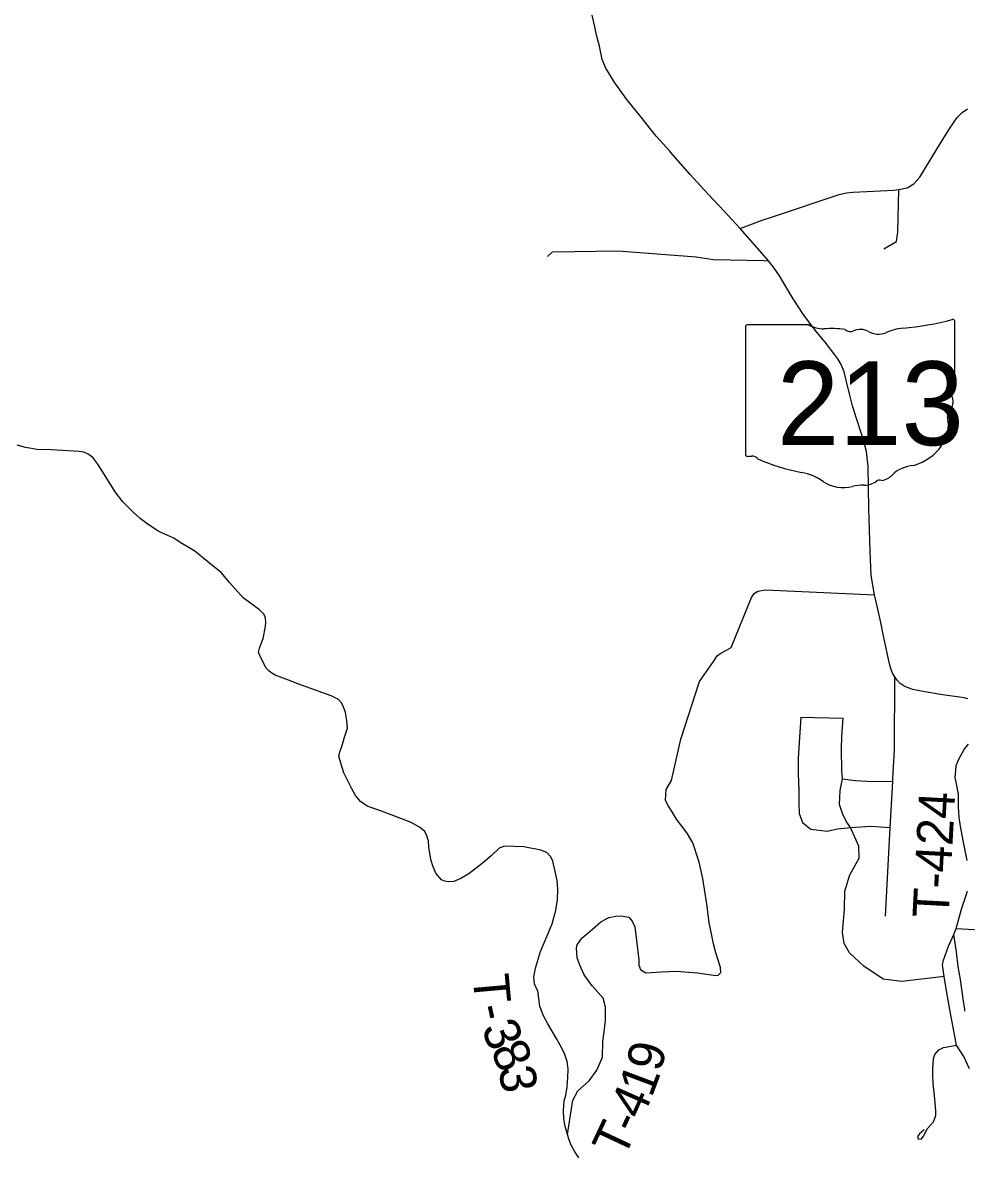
# Model space of a CAD drawing. Extents: x 2402298 to 2498138, y 789485 to 950881.
# Drawn here: x 2476688 to 2484526, y 874577 to 883995 of the extents above; entities that cross this region are included whole.
import ezdxf

# ---------------------------------------------------------------- set-up
doc = ezdxf.new("R2010")
doc.units = 0
for name, color, linetype in [('GM_X_State_Route', 7, 'Continuous'), ('GM_X_State_Shield', 7, 'Continuous'), ('GM_X_Township_Road', 7, 'Continuous'), ('GM_X_Township_Road_Text', 7, 'Continuous')]:
    doc.layers.add(name, color=color, linetype=linetype)

msp = doc.modelspace()

# ---------------------------------------------------------------- linework, layer by layer
at = {"layer": 'GM_X_State_Route'}
for points in [[(2482062.4, 882927.1), (2481950.2, 883051.3), (2481826.2, 883210.2), (2481705.4, 883356.5), (2481606.8, 883496.4), (2481530.5, 883617.2), (2481501.9, 883689.1), (2481479.4, 883800.2), (2481455, 883892.2), (2481439.4, 883959.9), (2481418.6, 884057.1)], [(2482646.9, 882284.5), (2482516.1, 882429.7), (2482346, 882609.4), (2482233.2, 882733.3), (2482069.4, 882919.3), (2482062.4, 882927.1)], [(2483763, 879242.9), (2483735.5, 879402), (2483727.3, 879605.7), (2483716.4, 879957.8), (2483710, 880308.3), (2483697.6, 880431.4), (2483675.6, 880514.4), (2483657.3, 880570), (2483613.4, 880706.9), (2483582.1, 880811.3), (2483558.2, 880900.3), (2483529.3, 881026.4), (2483511.1, 881094.2), (2483486.6, 881154.1), (2483459.6, 881201.3), (2483434.5, 881236.4), (2483352.8, 881340.2), (2483281.8, 881425.7), (2483226.1, 881498.2), (2483171.7, 881573), (2483086.5, 881700.7), (2482973.7, 881890.6), (2482923.9, 881963.5), (2482881.8, 882017), (2482831.2, 882078.5), (2482646.9, 882284.5)], [(2484540.1, 878377.2), (2484509.2, 878385.2), (2484312.9, 878413), (2484181.9, 878435.5), (2484081.1, 878456), (2484043.1, 878467.7), (2484011.1, 878483), (2483977.4, 878506), (2483951.1, 878532.5), (2483931.4, 878560.1), (2483913.9, 878591.3), (2483900.9, 878622.3), (2483890.6, 878655.8), (2483873.3, 878731.7), (2483851.9, 878838), (2483833.9, 878924.8), (2483815.8, 879011.1), (2483784.5, 879148.4), (2483763, 879242.9)]]:
    msp.add_lwpolyline(points, dxfattribs=at)
at = {"layer": 'GM_X_State_Shield'}
for p, q in [((2484431.7, 880958.8), (2484431.7, 881511.5)), ((2482691.5, 881467.2), (2482691.5, 880410.5)), ((2483218.3, 881485.3), (2482708.6, 881485.3)), ((2484431.5, 880958.9), (2484431.7, 880958.8))]:
    msp.add_line(p, q, dxfattribs=at)
for centre, major_axis, start_param, end_param in [((2483811.8, 882925.9), (1845.5, 0), 4.814394, 5.042369), ((2484412.4, 881513.8), (19.4, 0), 6.141152, 7.989035), ((2482711.4, 881469.4), (20.2, 0), 1.712693, 3.28349), ((2483339.6, 881608), (195.5, 0), 4.042523, 4.731795), ((2483404.5, 880892.1), (702, 0), 1.404758, 1.657858), ((2483563.8, 881474.9), (56.4, 0), 3.836095, 5.185415), ((2483646.6, 881352.8), (117.3, 0), 0.950623, 2.079405), ((2483798, 881520.3), (141.1, 0), 4.081561, 5.145723), ((2484047.2, 881162.6), (371.3, 0), 1.699011, 2.107814), ((2484427.2, 880918.2), (30, 0), 1.883978, 3.671073), ((2484411, 880956.6), (20.7, 0), 5.05454, 6.418171), ((2484236.5, 880848.3), (180, 0), 5.934695, 6.695948), ((2484501.1, 880727.5), (130.9, 0), 2.387724, 3.262537), ((2483915.2, 880657.2), (461.6, 0), 5.101752, 6.440018), ((2482711.6, 880408.2), (20.3, 0), 3.00124, 4.508301), ((2482714.7, 880516.3), (155.2, 0), 4.665946, 4.897461), ((2482746.5, 880349.6), (56, 0), 0.519207, 1.627899), ((2483453.1, 881298.9), (1332.7, 0), 4.195997, 4.488961), ((2484109.8, 880113.9), (252.8, 0), 1.647645, 2.488434), ((2483055.7, 879935.8), (417, 0), 0.823519, 1.323587), ((2483506.7, 880344.3), (264.6, 0), 4.026481, 4.996735), ((2483678.9, 880265.2), (141, 0), 4.691044, 5.507374), ((2483806.5, 880162.9), (39.7, 0), 1.147584, 2.315152), ((2483789.5, 880308.1), (149.1, 0), 4.937069, 5.64225), ((2483659.6, 879979), (217.4, 0), 1.495662, 1.94098)]:
    msp.add_ellipse(centre, major_axis=major_axis, ratio=0.8, start_param=start_param, end_param=end_param, dxfattribs=at)
at = {"layer": 'GM_X_Township_Road'}
for p, q in [((2483150.3, 878223.8), (2483503.5, 878215.5)), ((2484440.6, 876468.1), (2484743.1, 876451.3))]:
    msp.add_line(p, q, dxfattribs=at)
for points in [[(2482646.9, 882284.5), (2482831, 882353.7), (2482925, 882386.1), (2483470.4, 882567.8), (2483529.6, 882580.3), (2483584.3, 882586.5), (2483758.6, 882595.5), (2483919.6, 882603.1), (2483965.1, 882607.8), (2484035.8, 882622.1), (2484091.2, 882655.4), (2484139.1, 882711.1), (2484226.6, 882854.1), (2484280.6, 882943.1), (2484381.2, 883103.7), (2484418.8, 883162.8), (2484450.1, 883206.6), (2484492.6, 883248.3), (2484537, 883279.9)], [(2483841.8, 882115), (2483945.2, 882177), (2483957.9, 882254.9), (2483965.1, 882607.8)], [(2481048.6, 882051.5), (2481090.2, 882091.9), (2481635.5, 882098.3), (2482282.4, 882050.6), (2482427.1, 882028.3), (2482844.4, 882017.9), (2482881.8, 882017)], [(2481112.8, 876606.4), (2481129.7, 876706.6), (2481132.4, 876796.9), (2481126.7, 876868.6), (2481112.2, 876942.1), (2481090.5, 877028.2), (2481074.9, 877065.8), (2481042.7, 877099.8), (2480992.4, 877119), (2480851.6, 877146.6), (2480691.2, 877152.1), (2480645.4, 877135.6), (2480578.4, 877073.2), (2480505.7, 877009.6), (2480393, 876924.7), (2480327.4, 876885.3), (2480269.7, 876860.3), (2480221.3, 876857), (2480194.2, 876861.8), (2480167.3, 876873.5), (2480118.4, 876928.1), (2480097.9, 876982.4), (2480077.4, 877043.1), (2480062.8, 877144.8), (2480060, 877198.2), (2480044.4, 877238.1), (2480027.7, 877275.6), (2479985.2, 877312.4), (2479916.2, 877348.8), (2479828.4, 877384.1), (2479667.3, 877444.8), (2479549.4, 877485), (2479492.9, 877524.1), (2479453.8, 877574.5), (2479420.8, 877629.2), (2479355.9, 877763.8), (2479314.9, 877899.3), (2479322.9, 877937.6), (2479339.2, 877981.6), (2479362, 878058.6), (2479385.1, 878132.5), (2479380.7, 878196.7), (2479369.9, 878263.8), (2479350.6, 878316.5), (2479333.9, 878347.2), (2479312.5, 878373.2), (2479251, 878401.9), (2478972.9, 878502.2), (2478895.1, 878531.2), (2478784.2, 878574.9), (2478757.7, 878590.8), (2478734.6, 878607.9), (2478711.1, 878633.1), (2478677, 878694.8), (2478648, 878761.7), (2478657, 878806.8), (2478684.7, 878879.5), (2478705.3, 878977.9), (2478706.6, 879015.3), (2478705.9, 879048.1), (2478693, 879079), (2478654.4, 879117.6), (2478520.6, 879216.7), (2478406.7, 879342.8), (2478338.5, 879423.9), (2478226.5, 879516.5), (2478118.4, 879605.3), (2477996, 879675.3), (2477944, 879712.9), (2477818.5, 879768.8), (2477729.1, 879826.7), (2477664.8, 879876.2), (2477606.9, 879928.4), (2477519.3, 880013.3), (2477457.3, 880097.5), (2477379.2, 880220.8), (2477312, 880326.6), (2477270.3, 880381.6), (2477230.9, 880410.5), (2477196.7, 880427.9), (2477156.4, 880433.5), (2476924, 880446.1), (2476809, 880449.9), (2476711.9, 880466.6), (2476643.3, 880486)], [(2482426.8, 876342.8), (2482416.8, 876382.7), (2482389, 876519.5), (2482370.1, 876671.8), (2482336.7, 876885.4), (2482307.8, 877021), (2482254.4, 877181.2), (2482207.7, 877261.3), (2482118.7, 877377), (2482082.2, 877437.8), (2482046.9, 877493.2), (2482026.8, 877535.2), (2482034.3, 877623.3), (2482076.3, 877699.6), (2482155.3, 878042.8), (2482310.2, 878522.8), (2482427.2, 878686.8), (2482456, 878733.9), (2482487.9, 878756.7), (2482533.5, 878782.5), (2482573, 878805.3), (2482743.1, 879218.4), (2482765.2, 879252.6), (2482793.3, 879273.2), (2482857, 879282.2), (2483763, 879242.9)], [(2483916.3, 877716.5), (2483929.5, 877957.9), (2483931.4, 878560.1)], [(2483150.3, 878223.8), (2483129.4, 877885.1), (2483129.4, 877754.2), (2483133.6, 877617.1), (2483133.6, 877513.2), (2483137.8, 877423.8), (2483164.8, 877351.1), (2483233.4, 877295), (2483369.7, 877278.8), (2483455.7, 877297.1), (2483538, 877306.6)], [(2484342.3, 876070.3), (2483989.8, 876028.8), (2483834.4, 876049.5), (2483674.6, 876155.8), (2483554.9, 876268.2), (2483510.9, 876343.9), (2483498.7, 876436.8), (2483513.3, 876629.8), (2483518.2, 876778.9), (2483559.7, 876915.7), (2483635.5, 877055), (2483634.4, 877153.7), (2483563.8, 877309.5), (2483527.2, 877360), (2483497.3, 877423.8), (2483472.3, 877498.6), (2483478.6, 877615), (2483497.3, 877712.6), (2483493.1, 877781.2), (2483489, 877960), (2483491, 878068), (2483503.5, 878215.5)], [(2484532.8, 877034.3), (2484500.7, 877199.3), (2484477.8, 877319.5), (2484466, 877390.6), (2484461.7, 877479.4), (2484460, 877586.1), (2484444.8, 877670.8), (2484434.6, 877723.2), (2484438, 877780.8), (2484443.1, 877824.8), (2484463.4, 877877.2), (2484510.8, 877961.9), (2484544.7, 878000)], [(2483497.3, 877712.6), (2483605.3, 877698.1), (2483703, 877693.9), (2483914.9, 877691.9)], [(2483854.7, 876571.8), (2483894.2, 877309.5), (2483914.9, 877691.9), (2483916.3, 877716.5)], [(2483538, 877306.6), (2483563.8, 877309.5), (2483732.1, 877319.9), (2483894.2, 877309.5)], [(2484553.6, 875304.4), (2484505, 875407.1), (2484443.4, 875500.4), (2484395.8, 875764.7), (2484362.2, 875951.4), (2484342.3, 876070.3), (2484328.6, 876168.7), (2484337.3, 876206), (2484377.1, 876321.8), (2484422.6, 876419.5), (2484440.6, 876468.1), (2484485.4, 876629.7), (2484535.4, 876779.5)], [(2481308.7, 874564.5), (2481271.6, 874619.5), (2481242, 874676), (2481223.4, 874723.1), (2481214.3, 874758.7), (2481194.8, 874824.6), (2481182.8, 874889.2), (2481180.1, 874956.4), (2481185.4, 875036.4), (2481199.9, 875084.6), (2481210.5, 875154), (2481216.2, 875230.6), (2481218.5, 875304.6), (2481210.1, 875364.5), (2481191.1, 875421.8), (2481167.3, 875475.7), (2481125.1, 875549.6), (2481049.7, 875676), (2481010.2, 875748.4), (2480984.8, 875823.5), (2480967.6, 875950.1), (2480952.5, 875976), (2480938.5, 876009), (2480934.3, 876064), (2480948, 876139.5), (2480990.1, 876277.2), (2481050, 876421.6), (2481085.7, 876508.2), (2481111.9, 876601.2), (2481112.8, 876606.4)], [(2481214.3, 874758.7), (2481256.8, 875042.5), (2481299.1, 875120.4), (2481394.7, 875202.7), (2481457, 875291.7), (2481503.7, 875400.6), (2481508.2, 875534.1), (2481517.1, 875612), (2481530.4, 875705.4), (2481528.2, 875816.6), (2481510.4, 875890), (2481419.2, 875992.3), (2481352.5, 876085.7), (2481316.9, 876163.6), (2481293.5, 876224.8), (2481289.1, 876304.8), (2481294.6, 876334.9), (2481333.6, 876389.4), (2481420.3, 876463.9), (2481489.3, 876523.9), (2481557.1, 876560.6), (2481613.8, 876572.9), (2481660.7, 876573.7), (2481722.8, 876564), (2481749.5, 876529.5), (2481771.7, 876482.8), (2481787.3, 876370.4), (2481805.1, 876210.3), (2481807.3, 876165.8), (2481820.7, 876129.1), (2481865.1, 876101.3), (2481993.1, 876109.1), (2482116.5, 876113.5), (2482292.2, 876100.2), (2482370.1, 876089.1), (2482426.8, 876081.3), (2482462.4, 876080.2), (2482486.9, 876102.4), (2482484.6, 876144.7), (2482445.7, 876268.1), (2482426.8, 876342.8)], [(2484514.6, 875781.4), (2484514.4, 875797.4), (2484501.3, 875885.1), (2484476.7, 876045.4), (2484459.3, 876152.5), (2484444.3, 876275.7), (2484422.6, 876419.5)], [(2484176.7, 874797.3), (2484155.9, 874779), (2484136.4, 874764.3), (2484119.3, 874741.1), (2484126.6, 874721.6), (2484152.2, 874720.4), (2484173, 874746), (2484199.9, 874805.9), (2484253.7, 874862.1), (2484273.2, 874915.8), (2484272, 874957.3), (2484262.2, 875080.7), (2484251.2, 875182.1), (2484248.8, 875253), (2484248.8, 875295.8), (2484254.9, 875388.6), (2484265.9, 875422.8), (2484297.6, 875461.9), (2484335.5, 875480.2), (2484443.4, 875500.4)]]:
    msp.add_lwpolyline(points, dxfattribs=at)

# ---------------------------------------------------------------- texts
at = {"layer": 'GM_X_State_Shield'}
msp.add_text('213', height=696.1, dxfattribs=at).set_placement((2482952.7, 880485))
at = {"layer": 'GM_X_Township_Road_Text'}
for s, rotation, p in [('T-424', 86.91303, (2484377.8, 876551.1)), ('T', 275.14089, (2480424.7, 876079.2)), ('-', 282.25453, (2480450.9, 875815.6)), ('3', 292.26922, (2480494, 875640.7)), ('8', 294.70403, (2480569.6, 875456.9)), ('9', 76.79652, (2481989.4, 875270.8)), ('3', 278.3612, (2480640.4, 875310.7)), ('1', 69.38086, (2481912, 875057.4)), ('4', 66.14471, (2481830.3, 874871.3)), ('-', 65.17252, (2481776.3, 874754.4)), ('T', 64.92045, (2481680.6, 874549.9))]:
    msp.add_text(s, height=300, rotation=rotation, dxfattribs=at).set_placement(p)

doc.saveas('drawing.dxf')
